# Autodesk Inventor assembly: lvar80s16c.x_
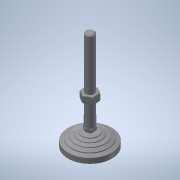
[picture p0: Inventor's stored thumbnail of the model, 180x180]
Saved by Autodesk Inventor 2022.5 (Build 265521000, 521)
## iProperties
Part Number: lvar80s16c.x_
Material: 一般
Document SubType Name: Assembly
Designer: ImaoCorp
Sending System: SOLIDWORKS 2017-2017317
MC: AMD64
MC_MODEL: Intel64 Family 6 Model 60 Stepping 3, GenuineIntel
OS: Windows_NT
FRU: Parasolid Version 29.0, build 201,  4-17-2017
FORMAT: text
GUISE: transmit
KEY: lvar80s16c
FILE: lvar80s16c.x_t
DATE: Mon Jul 01 18:16:13 2019
Author: ImaoCorp
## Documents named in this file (3)
- X:\14_SW2022-Inv2022\00_全2023-1023新製品(TCC)まで\l\lvar80s16c\LVAR80S16C.iam
- X:\14_SW2022-Inv2022\00_全2023-1023新製品(TCC)まで\l\lvar80s16c\lvar80s16c_01.ipt
- X:\14_SW2022-Inv2022\00_全2023-1023新製品(TCC)まで\l\lvar80s16c\lvar80s16c_02.ipt
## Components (2 placed, 2 different names)
1. lvar80s16c_01
2. lvar80s16c_02
